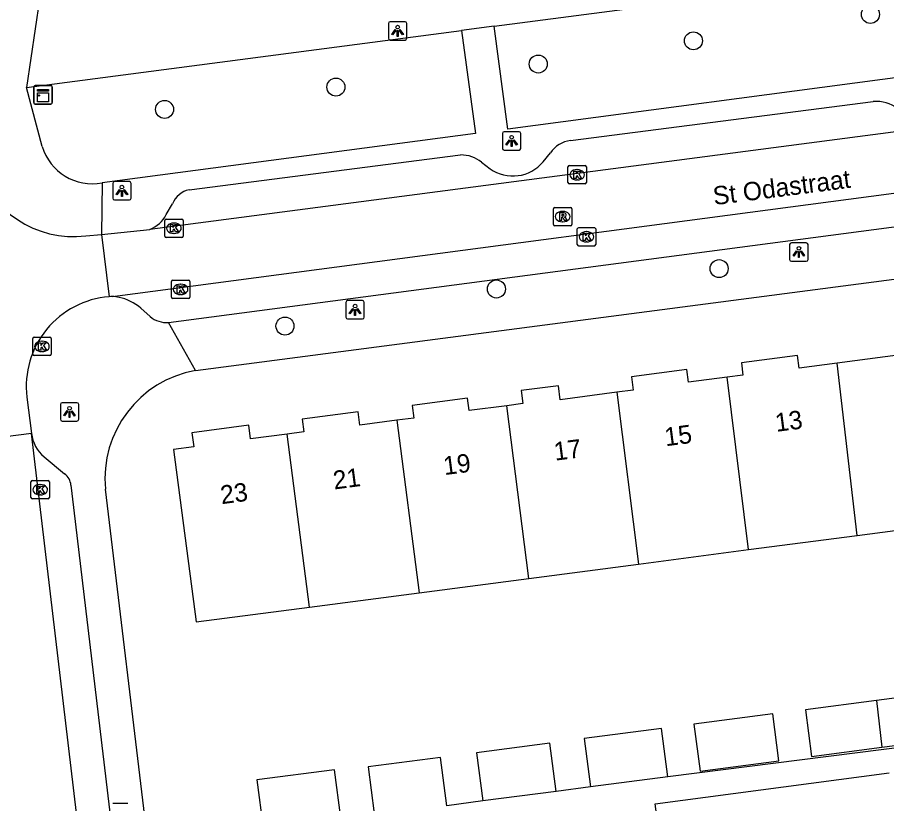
# Model space of a CAD drawing. Extents: x 162074 to 163034, y 381824 to 382557.
# Drawn here: x 162347.28 to 162394.48, y 382422.66 to 382465.37 of the extents above; entities that cross this region are included whole.
import ezdxf

# ---------------------------------------------------------------- set-up
doc = ezdxf.new("R2010")
doc.units = 0
for name, color, linetype in [('IMGEO_Boom', 7, 'Continuous'), ('IMGEO_Kast', 7, 'Continuous'), ('IMGEO_Kolk', 7, 'Continuous'), ('IMGEO_Lichtpunt', 7, 'Continuous'), ('IMGEO_Openbare_ruimte_label', 7, 'Continuous'), ('IMGEO_Pand', 7, 'Continuous'), ('IMGEO_Pand_nummerreeks', 7, 'Continuous'), ('IMGEO_Rijbaan_lokaal_open', 7, 'Continuous'), ('IMGEO_Rioolput', 7, 'Continuous'), ('IMGEO_Voetpad_open', 7, 'Continuous')]:
    doc.layers.add(name, color=color, linetype=linetype)

msp = doc.modelspace()

# ---------------------------------------------------------------- linework, layer by layer
at = {"layer": 'IMGEO_Boom'}
for centre in [(162393.602, 382465.53), (162383.992, 382464.098), (162375.562, 382462.838), (162364.577, 382461.583), (162355.268, 382460.371), (162385.387, 382451.722), (162373.292, 382450.616), (162361.81, 382448.6)]:
    msp.add_circle(centre, 0.489, dxfattribs=at)
at = {"layer": 'IMGEO_Kast'}
for p, q in [((162348.168, 382460.739), (162348.168, 382461.58)), ((162348.168, 382461.58), (162348.168, 382460.739)), ((162348.243, 382461.664), (162349.084, 382461.664)), ((162349.084, 382461.664), (162348.243, 382461.664)), ((162349.168, 382461.589), (162349.168, 382460.748)), ((162349.168, 382460.748), (162349.168, 382461.589)), ((162349.093, 382460.664), (162348.252, 382460.664)), ((162348.252, 382460.664), (162349.093, 382460.664))]:
    msp.add_line(p, q, dxfattribs=at)
for points in [[(162348.363, 382461.454), (162348.963, 382461.454), (162348.963, 382461.369), (162348.363, 382461.369), (162348.363, 382461.454)], [(162348.363, 382461.279), (162348.963, 382461.279), (162348.963, 382460.79), (162348.363, 382460.79), (162348.363, 382461.279)]]:
    msp.add_lwpolyline(points, dxfattribs=at)
msp.add_circle((162348.447, 382461.128), 0.0377, dxfattribs=at)
for centre, start, end in [((162348.246, 382461.586), 92.4484, 184.2845), ((162348.246, 382461.586), 92.4484, 184.2845), ((162349.09, 382461.586), 2.4484, 94.2845), ((162349.09, 382461.586), 2.4484, 94.2845), ((162348.246, 382460.742), 182.4484, 274.2845), ((162348.246, 382460.742), 182.4484, 274.2845), ((162349.09, 382460.742), 272.4484, 4.2845), ((162349.09, 382460.742), 272.4484, 4.2845)]:
    msp.add_arc(centre, 0.0779, start, end, dxfattribs=at)
at = {"layer": 'IMGEO_Kolk'}
for p, q in [((162377.175, 382456.395), (162377.175, 382457.247)), ((162377.25, 382457.321), (162378.102, 382457.321)), ((162378.176, 382457.247), (162378.176, 382456.395)), ((162377.663, 382457.101), (162377.688, 382457.101)), ((162378.102, 382456.321), (162377.25, 382456.321)), ((162377.686, 382456.541), (162377.661, 382456.541)), ((162355.277, 382453.488), (162355.277, 382454.34)), ((162355.352, 382454.414), (162356.204, 382454.414)), ((162356.278, 382454.34), (162356.278, 382453.488)), ((162355.765, 382454.194), (162355.79, 382454.194)), ((162377.683, 382453.025), (162377.683, 382453.877)), ((162377.758, 382453.951), (162378.61, 382453.951)), ((162378.684, 382453.877), (162378.684, 382453.025)), ((162356.204, 382453.414), (162355.352, 382453.414)), ((162355.788, 382453.634), (162355.763, 382453.634)), ((162378.171, 382453.731), (162378.196, 382453.731)), ((162378.61, 382452.951), (162377.758, 382452.951)), ((162378.194, 382453.171), (162378.169, 382453.171)), ((162355.639, 382450.169), (162355.639, 382451.021)), ((162355.714, 382451.095), (162356.566, 382451.095)), ((162356.64, 382451.021), (162356.64, 382450.169)), ((162356.127, 382450.875), (162356.152, 382450.875)), ((162356.566, 382450.095), (162355.714, 382450.095)), ((162356.15, 382450.315), (162356.125, 382450.315)), ((162348.11, 382447.071), (162348.11, 382447.923)), ((162348.185, 382447.997), (162349.037, 382447.997)), ((162348.598, 382447.777), (162348.623, 382447.777)), ((162349.111, 382447.923), (162349.111, 382447.071)), ((162348.621, 382447.217), (162348.596, 382447.217)), ((162349.037, 382446.997), (162348.185, 382446.997)), ((162348.015, 382439.284), (162348.015, 382440.136)), ((162348.09, 382440.21), (162348.942, 382440.21)), ((162349.016, 382440.136), (162349.016, 382439.284)), ((162348.503, 382439.99), (162348.528, 382439.99)), ((162348.942, 382439.21), (162348.09, 382439.21)), ((162348.526, 382439.43), (162348.501, 382439.43))]:
    msp.add_line(p, q, dxfattribs=at)
for points in [[(162377.175, 382456.395), (162377.175, 382457.247)], [(162377.25, 382457.321), (162378.102, 382457.321)], [(162378.176, 382457.247), (162378.176, 382456.395)], [(162377.496, 382457.021), (162377.619, 382457.021), (162377.619, 382456.87), (162377.749, 382457.021), (162377.913, 382457.021), (162377.767, 382456.87), (162377.92, 382456.621), (162377.768, 382456.621), (162377.683, 382456.785), (162377.619, 382456.718), (162377.619, 382456.621), (162377.496, 382456.621), (162377.496, 382457.021)], [(162378.102, 382456.321), (162377.25, 382456.321)], [(162355.277, 382453.488), (162355.277, 382454.34)], [(162355.352, 382454.414), (162356.204, 382454.414)], [(162356.278, 382454.34), (162356.278, 382453.488)], [(162355.598, 382454.114), (162355.721, 382454.114), (162355.721, 382453.963), (162355.851, 382454.114), (162356.015, 382454.114), (162355.869, 382453.963), (162356.022, 382453.714), (162355.87, 382453.714), (162355.785, 382453.878), (162355.721, 382453.811), (162355.721, 382453.714), (162355.598, 382453.714), (162355.598, 382454.114)], [(162377.683, 382453.025), (162377.683, 382453.877)], [(162377.758, 382453.951), (162378.61, 382453.951)], [(162378.684, 382453.877), (162378.684, 382453.025)], [(162356.204, 382453.414), (162355.352, 382453.414)], [(162378.004, 382453.651), (162378.127, 382453.651), (162378.127, 382453.5), (162378.257, 382453.651), (162378.421, 382453.651), (162378.275, 382453.5), (162378.428, 382453.251), (162378.276, 382453.251), (162378.191, 382453.415), (162378.127, 382453.348), (162378.127, 382453.251), (162378.004, 382453.251), (162378.004, 382453.651)], [(162378.61, 382452.951), (162377.758, 382452.951)], [(162355.639, 382450.169), (162355.639, 382451.021)], [(162355.714, 382451.095), (162356.566, 382451.095)], [(162356.64, 382451.021), (162356.64, 382450.169)], [(162355.96, 382450.795), (162356.083, 382450.795), (162356.083, 382450.644), (162356.213, 382450.795), (162356.377, 382450.795), (162356.231, 382450.644), (162356.384, 382450.395), (162356.232, 382450.395), (162356.147, 382450.559), (162356.083, 382450.492), (162356.083, 382450.395), (162355.96, 382450.395), (162355.96, 382450.795)], [(162356.566, 382450.095), (162355.714, 382450.095)], [(162348.11, 382447.071), (162348.11, 382447.923)], [(162348.185, 382447.997), (162349.037, 382447.997)], [(162348.431, 382447.697), (162348.554, 382447.697), (162348.554, 382447.546), (162348.684, 382447.697), (162348.848, 382447.697), (162348.702, 382447.546), (162348.855, 382447.297), (162348.703, 382447.297), (162348.618, 382447.461), (162348.554, 382447.394), (162348.554, 382447.297), (162348.431, 382447.297), (162348.431, 382447.697)], [(162349.111, 382447.923), (162349.111, 382447.071)], [(162349.037, 382446.997), (162348.185, 382446.997)], [(162348.015, 382439.284), (162348.015, 382440.136)], [(162348.09, 382440.21), (162348.942, 382440.21)], [(162349.016, 382440.136), (162349.016, 382439.284)], [(162348.336, 382439.91), (162348.459, 382439.91), (162348.459, 382439.759), (162348.589, 382439.91), (162348.753, 382439.91), (162348.607, 382439.759), (162348.76, 382439.51), (162348.608, 382439.51), (162348.523, 382439.674), (162348.459, 382439.607), (162348.459, 382439.51), (162348.336, 382439.51), (162348.336, 382439.91)], [(162348.942, 382439.21), (162348.09, 382439.21)]]:
    msp.add_lwpolyline(points, dxfattribs=at)
for centre, start, end in [((162377.252, 382457.245), 91.552, 178.448), ((162377.252, 382457.245), 91.552, 178.448), ((162378.1, 382457.245), 1.552, 88.448), ((162378.1, 382457.245), 1.552, 88.448), ((162377.252, 382456.397), 181.552, 268.448), ((162377.252, 382456.397), 181.552, 268.448), ((162378.1, 382456.397), 271.552, 358.448), ((162378.1, 382456.397), 271.552, 358.448), ((162355.354, 382454.338), 91.552, 178.448), ((162355.354, 382454.338), 91.552, 178.448), ((162356.202, 382454.338), 1.552, 88.448), ((162356.202, 382454.338), 1.552, 88.448), ((162377.76, 382453.875), 91.552, 178.448), ((162377.76, 382453.875), 91.552, 178.448), ((162378.608, 382453.875), 1.552, 88.448), ((162378.608, 382453.875), 1.552, 88.448), ((162355.354, 382453.49), 181.552, 268.448), ((162355.354, 382453.49), 181.552, 268.448), ((162356.202, 382453.49), 271.552, 358.448), ((162356.202, 382453.49), 271.552, 358.448), ((162377.76, 382453.027), 181.552, 268.448), ((162377.76, 382453.027), 181.552, 268.448), ((162378.608, 382453.027), 271.552, 358.448), ((162378.608, 382453.027), 271.552, 358.448), ((162355.716, 382451.019), 91.552, 178.448), ((162355.716, 382451.019), 91.552, 178.448), ((162356.564, 382451.019), 1.552, 88.448), ((162356.564, 382451.019), 1.552, 88.448), ((162355.716, 382450.171), 181.552, 268.448), ((162355.716, 382450.171), 181.552, 268.448), ((162356.564, 382450.171), 271.552, 358.448), ((162356.564, 382450.171), 271.552, 358.448), ((162348.187, 382447.921), 91.552, 178.448), ((162348.187, 382447.921), 91.552, 178.448), ((162349.035, 382447.921), 1.552, 88.448), ((162349.035, 382447.921), 1.552, 88.448), ((162348.187, 382447.073), 181.552, 268.448), ((162348.187, 382447.073), 181.552, 268.448), ((162349.035, 382447.073), 271.552, 358.448), ((162349.035, 382447.073), 271.552, 358.448), ((162348.092, 382440.134), 91.552, 178.448), ((162348.092, 382440.134), 91.552, 178.448), ((162348.94, 382440.134), 1.552, 88.448), ((162348.94, 382440.134), 1.552, 88.448), ((162348.092, 382439.286), 181.552, 268.448), ((162348.092, 382439.286), 181.552, 268.448), ((162348.94, 382439.286), 271.552, 358.448), ((162348.94, 382439.286), 271.552, 358.448)]:
    msp.add_arc(centre, 0.0765, start, end, dxfattribs=at)
for centre, major_axis, ratio, start_param, end_param in [((162377.662, 382456.821), (-0.387, 0.002), 0.722429, 4.712389, 7.853982), ((162377.687, 382456.821), (-0.39, 0.002), 0.717154, 1.570796, 4.712389), ((162355.764, 382453.914), (-0.387, 0.002), 0.722429, 4.712389, 7.853982), ((162355.789, 382453.914), (-0.39, 0.002), 0.717154, 1.570796, 4.712389), ((162378.17, 382453.451), (-0.387, 0.002), 0.722429, 4.712389, 7.853982), ((162378.195, 382453.451), (-0.39, 0.002), 0.717154, 1.570796, 4.712389), ((162356.126, 382450.595), (-0.387, 0.002), 0.722429, 4.712389, 7.853982), ((162356.151, 382450.595), (-0.39, 0.002), 0.717154, 1.570796, 4.712389), ((162348.597, 382447.497), (-0.387, 0.002), 0.722429, 4.712389, 7.853982), ((162348.622, 382447.497), (-0.39, 0.002), 0.717154, 1.570796, 4.712389), ((162348.502, 382439.71), (-0.387, 0.002), 0.722429, 4.712389, 7.853982), ((162348.527, 382439.71), (-0.39, 0.002), 0.717154, 1.570796, 4.712389)]:
    msp.add_ellipse(centre, major_axis=major_axis, ratio=ratio, start_param=start_param, end_param=end_param, dxfattribs=at)
at = {"layer": 'IMGEO_Lichtpunt'}
for p, q in [((162368.33, 382465.137), (162367.522, 382465.137)), ((162368.33, 382465.137), (162367.522, 382465.137)), ((162367.428, 382465.042), (162367.428, 382464.235)), ((162367.428, 382465.042), (162367.428, 382464.235)), ((162368.424, 382464.235), (162368.424, 382465.042)), ((162368.424, 382464.235), (162368.424, 382465.042)), ((162367.522, 382464.141), (162368.33, 382464.141)), ((162367.522, 382464.141), (162368.33, 382464.141)), ((162373.619, 382459.06), (162373.619, 382458.253)), ((162373.619, 382459.06), (162373.619, 382458.253)), ((162374.521, 382459.155), (162373.713, 382459.155)), ((162374.521, 382459.155), (162373.713, 382459.155)), ((162374.615, 382458.253), (162374.615, 382459.06)), ((162374.615, 382458.253), (162374.615, 382459.06)), ((162373.713, 382458.159), (162374.521, 382458.159)), ((162373.713, 382458.159), (162374.521, 382458.159)), ((162352.457, 382456.353), (162352.457, 382455.546)), ((162352.457, 382456.353), (162352.457, 382455.546)), ((162353.359, 382456.448), (162352.551, 382456.448)), ((162353.359, 382456.448), (162352.551, 382456.448)), ((162353.453, 382455.546), (162353.453, 382456.353)), ((162353.453, 382455.546), (162353.453, 382456.353)), ((162352.551, 382455.452), (162353.359, 382455.452)), ((162352.551, 382455.452), (162353.359, 382455.452)), ((162389.216, 382453.029), (162389.216, 382452.222)), ((162389.216, 382453.029), (162389.216, 382452.222)), ((162390.118, 382453.124), (162389.31, 382453.124)), ((162390.118, 382453.124), (162389.31, 382453.124)), ((162390.212, 382452.222), (162390.212, 382453.029)), ((162390.212, 382452.222), (162390.212, 382453.029)), ((162389.31, 382452.128), (162390.118, 382452.128)), ((162389.31, 382452.128), (162390.118, 382452.128)), ((162365.115, 382449.89), (162365.115, 382449.083)), ((162365.115, 382449.89), (162365.115, 382449.083)), ((162366.017, 382449.985), (162365.209, 382449.985)), ((162366.017, 382449.985), (162365.209, 382449.985)), ((162366.111, 382449.083), (162366.111, 382449.89)), ((162366.111, 382449.083), (162366.111, 382449.89)), ((162365.209, 382448.989), (162366.017, 382448.989)), ((162365.209, 382448.989), (162366.017, 382448.989)), ((162350.513, 382444.438), (162349.705, 382444.438)), ((162350.513, 382444.438), (162349.705, 382444.438)), ((162349.611, 382444.343), (162349.611, 382443.536)), ((162349.611, 382444.343), (162349.611, 382443.536)), ((162350.607, 382443.536), (162350.607, 382444.343)), ((162350.607, 382443.536), (162350.607, 382444.343)), ((162349.705, 382443.442), (162350.513, 382443.442)), ((162349.705, 382443.442), (162350.513, 382443.442)), ((162353.269, 382422.66), (162352.461, 382422.66)), ((162353.269, 382422.66), (162352.461, 382422.66))]:
    msp.add_line(p, q, dxfattribs=at)
for points in [[(162367.802, 382464.706), (162367.841, 382464.678), (162367.653, 382464.416), (162367.615, 382464.443), (162367.802, 382464.706)], [(162368.014, 382464.678), (162368.052, 382464.705), (162368.239, 382464.443), (162368.2, 382464.415), (162368.014, 382464.678)], [(162367.904, 382464.658), (162367.951, 382464.658), (162367.951, 382464.336), (162367.904, 382464.336), (162367.904, 382464.658)], [(162373.993, 382458.724), (162374.032, 382458.696), (162373.844, 382458.434), (162373.806, 382458.461), (162373.993, 382458.724)], [(162374.095, 382458.676), (162374.142, 382458.676), (162374.142, 382458.354), (162374.095, 382458.354), (162374.095, 382458.676)], [(162374.205, 382458.696), (162374.243, 382458.723), (162374.43, 382458.461), (162374.391, 382458.433), (162374.205, 382458.696)], [(162352.831, 382456.017), (162352.87, 382455.989), (162352.682, 382455.727), (162352.644, 382455.754), (162352.831, 382456.017)], [(162352.933, 382455.969), (162352.98, 382455.969), (162352.98, 382455.647), (162352.933, 382455.647), (162352.933, 382455.969)], [(162353.043, 382455.989), (162353.081, 382456.016), (162353.268, 382455.754), (162353.229, 382455.726), (162353.043, 382455.989)], [(162389.59, 382452.693), (162389.629, 382452.665), (162389.441, 382452.403), (162389.403, 382452.43), (162389.59, 382452.693)], [(162389.692, 382452.645), (162389.739, 382452.645), (162389.739, 382452.323), (162389.692, 382452.323), (162389.692, 382452.645)], [(162389.802, 382452.665), (162389.84, 382452.692), (162390.027, 382452.43), (162389.988, 382452.402), (162389.802, 382452.665)], [(162365.489, 382449.554), (162365.528, 382449.526), (162365.34, 382449.264), (162365.302, 382449.291), (162365.489, 382449.554)], [(162365.591, 382449.506), (162365.638, 382449.506), (162365.638, 382449.184), (162365.591, 382449.184), (162365.591, 382449.506)], [(162365.701, 382449.526), (162365.739, 382449.553), (162365.926, 382449.291), (162365.887, 382449.263), (162365.701, 382449.526)], [(162349.985, 382444.007), (162350.024, 382443.979), (162349.836, 382443.717), (162349.798, 382443.744), (162349.985, 382444.007)], [(162350.087, 382443.959), (162350.134, 382443.959), (162350.134, 382443.637), (162350.087, 382443.637), (162350.087, 382443.959)], [(162350.197, 382443.979), (162350.235, 382444.006), (162350.422, 382443.744), (162350.383, 382443.716), (162350.197, 382443.979)]]:
    msp.add_lwpolyline(points, dxfattribs=at)
for centre in [(162367.927, 382464.84), (162374.118, 382458.858), (162352.956, 382456.151), (162389.715, 382452.827), (162365.614, 382449.688), (162350.11, 382444.141)]:
    msp.add_circle(centre, 0.0994, dxfattribs=at)
for centre, start, end in [((162367.522, 382465.042), 90, 180), ((162367.522, 382465.042), 90, 180), ((162368.33, 382465.042), 0, 90), ((162368.33, 382465.042), 0, 90), ((162367.522, 382464.235), 180, 270), ((162367.522, 382464.235), 180, 270), ((162368.33, 382464.235), 270, 0), ((162368.33, 382464.235), 270, 360), ((162373.713, 382459.06), 90, 180), ((162373.713, 382459.06), 90, 180), ((162374.521, 382459.06), 0, 90), ((162374.521, 382459.06), 0, 90), ((162373.713, 382458.253), 180, 270), ((162373.713, 382458.253), 180, 270), ((162374.521, 382458.253), 270, 0), ((162374.521, 382458.253), 270, 360), ((162352.551, 382456.353), 90, 180), ((162352.551, 382456.353), 90, 180), ((162353.359, 382456.353), 0, 90), ((162353.359, 382456.353), 0, 90), ((162352.551, 382455.546), 180, 270), ((162352.551, 382455.546), 180, 270), ((162353.359, 382455.546), 270, 0), ((162353.359, 382455.546), 270, 360), ((162389.31, 382453.029), 90, 180), ((162389.31, 382453.029), 90, 180), ((162390.118, 382453.029), 0, 90), ((162390.118, 382453.029), 0, 90), ((162389.31, 382452.222), 180, 270), ((162389.31, 382452.222), 180, 270), ((162390.118, 382452.222), 270, 0), ((162390.118, 382452.222), 270, 360), ((162365.209, 382449.89), 90, 180), ((162365.209, 382449.89), 90, 180), ((162366.017, 382449.89), 0, 90), ((162366.017, 382449.89), 0, 90), ((162365.209, 382449.083), 180, 270), ((162365.209, 382449.083), 180, 270), ((162366.017, 382449.083), 270, 0), ((162366.017, 382449.083), 270, 360), ((162349.705, 382444.343), 90, 180), ((162349.705, 382444.343), 90, 180), ((162350.513, 382444.343), 0, 90), ((162350.513, 382444.343), 0, 90), ((162349.705, 382443.536), 180, 270), ((162349.705, 382443.536), 180, 270), ((162350.513, 382443.536), 270, 0), ((162350.513, 382443.536), 270, 360)]:
    msp.add_arc(centre, 0.0946, start, end, dxfattribs=at)
at = {"layer": 'IMGEO_Pand'}
for points in [[(162392.89, 382437.23), (162404.853, 382438.794), (162404.44, 382441.957), (162398.784, 382441.218), (162397.976, 382447.401), (162391.801, 382446.593)], [(162391.801, 382446.593), (162389.725, 382446.322), (162389.637, 382446.996), (162386.592, 382446.598), (162386.679, 382445.934), (162385.824, 382445.822)], [(162392.89, 382437.23), (162391.801, 382446.593)], [(162385.824, 382445.822), (162383.726, 382445.548), (162383.635, 382446.244), (162380.628, 382445.851), (162380.723, 382445.123), (162379.833, 382445.006)], [(162386.972, 382436.456), (162385.824, 382445.822)], [(162379.833, 382445.006), (162376.76, 382444.604), (162376.661, 382445.364), (162374.642, 382445.1), (162374.734, 382444.392), (162373.862, 382444.278)], [(162379.833, 382445.006), (162381.014, 382435.677)], [(162373.862, 382444.278), (162371.814, 382444.01), (162371.726, 382444.682), (162368.714, 382444.288), (162368.803, 382443.603), (162367.889, 382443.484)], [(162367.889, 382443.484), (162365.878, 382443.221), (162365.783, 382443.943), (162362.749, 382443.547), (162362.839, 382442.857), (162361.935, 382442.739)], [(162375.057, 382434.898), (162373.862, 382444.278)], [(162367.889, 382443.484), (162369.099, 382434.119)], [(162361.935, 382442.739), (162359.943, 382442.478), (162359.846, 382443.215), (162356.757, 382442.811), (162356.859, 382442.037), (162355.76, 382441.893), (162356.984, 382432.535), (162363.15, 382433.341)], [(162363.15, 382433.341), (162361.935, 382442.739)], [(162386.972, 382436.456), (162392.89, 382437.23)], [(162381.014, 382435.677), (162386.972, 382436.456)], [(162375.057, 382434.898), (162381.014, 382435.677)], [(162369.099, 382434.119), (162375.057, 382434.898)], [(162363.15, 382433.341), (162369.099, 382434.119)], [(162394.228, 382425.722), (162398.434, 382426.272), (162398.101, 382428.812), (162393.933, 382428.266)], [(162393.933, 382428.266), (162390.075, 382427.762), (162390.408, 382425.223), (162394.228, 382425.722)], [(162393.933, 382428.266), (162394.228, 382425.722)], [(162388.627, 382424.99), (162388.295, 382427.529), (162384.019, 382426.97), (162384.351, 382424.43), (162388.627, 382424.99)], [(162382.601, 382424.117), (162382.258, 382426.74), (162378.063, 382426.191), (162378.405, 382423.569)], [(162376.532, 382423.323), (162376.197, 382425.947), (162372.209, 382425.425), (162372.552, 382422.803)], [(162370.594, 382422.547), (162370.255, 382425.17), (162366.319, 382424.655), (162366.651, 382422.117)], [(162364.846, 382421.889), (162364.504, 382424.503), (162360.286, 382423.951), (162360.628, 382421.338)], [(162382.601, 382424.117), (162378.405, 382423.569)], [(162376.532, 382423.323), (162372.552, 382422.803)]]:
    msp.add_lwpolyline(points, dxfattribs=at)
at = {"layer": 'IMGEO_Rijbaan_lokaal_open'}
for points in [[(162463.823, 382468.189), (162354.468, 382453.854)], [(162352.448, 382450.209), (162401.436, 382456.696)], [(162351.85, 382453.585), (162354.468, 382453.854)], [(162350.989, 382453.496), (162351.85, 382453.585)], [(162351.85, 382453.585), (162352.256, 382450.197)], [(162352.448, 382450.209), (162352.352, 382450.204), (162352.256, 382450.197)], [(162347.791, 382444.746), (162348.044, 382442.765)], [(162348.044, 382442.765), (162343.079, 382442.137)], [(162359.505, 382347.328), (162351.073, 382417.25), (162348.044, 382442.765)]]:
    msp.add_lwpolyline(points, dxfattribs=at)
for centre, radius, start, end in [((162350.348, 382459.007), 5.548, 196.1891, 276.6348), ((162352.649, 382445.321), 4.892, 94.6048, 186.7523)]:
    msp.add_arc(centre, radius, start, end, dxfattribs=at)
at = {"layer": 'IMGEO_Rioolput'}
for p, q in [((162376.389, 382454.124), (162376.389, 382454.976)), ((162376.464, 382455.05), (162377.316, 382455.05)), ((162376.877, 382454.83), (162376.902, 382454.83)), ((162377.39, 382454.976), (162377.39, 382454.124)), ((162377.316, 382454.05), (162376.464, 382454.05)), ((162376.9, 382454.27), (162376.875, 382454.27))]:
    msp.add_line(p, q, dxfattribs=at)
for points in [[(162376.389, 382454.124), (162376.389, 382454.976)], [(162376.464, 382455.05), (162377.316, 382455.05)], [(162376.978, 382454.748), (162376.726, 382454.75), (162376.726, 382454.35)], [(162377.39, 382454.976), (162377.39, 382454.124)], [(162376.726, 382454.35), (162376.85, 382454.35), (162376.85, 382454.512), (162376.861, 382454.512)], [(162376.904, 382454.669), (162376.85, 382454.669), (162376.85, 382454.588)], [(162376.85, 382454.588), (162376.902, 382454.588)], [(162376.908, 382454.483), (162376.979, 382454.35), (162377.119, 382454.35), (162377.054, 382454.476)], [(162377.316, 382454.05), (162376.464, 382454.05)]]:
    msp.add_lwpolyline(points, dxfattribs=at)
for centre, radius, start, end in [((162376.466, 382454.974), 0.0765, 91.552, 178.448), ((162376.466, 382454.974), 0.0765, 91.552, 178.448), ((162377.314, 382454.974), 0.0765, 1.552, 88.448), ((162377.314, 382454.974), 0.0765, 1.552, 88.448), ((162376.86, 382454.459), 0.0533, 26.0293, 88.6989), ((162376.886, 382454.777), 0.19, 274.7715, 282.9687), ((162376.91, 382454.573), 0.0964, 77.0061, 93.1865), ((162376.924, 382454.63), 0.0378, 276.6634, 79.6772), ((162376.977, 382454.638), 0.109, 350.3612, 89.416), ((162376.975, 382454.638), 0.112, 277.5842, 350.9817), ((162376.959, 382454.423), 0.108, 29.5134, 73.7905), ((162376.466, 382454.126), 0.0765, 181.552, 268.448), ((162376.466, 382454.126), 0.0765, 181.552, 268.448), ((162377.314, 382454.126), 0.0765, 271.552, 358.448), ((162377.314, 382454.126), 0.0765, 271.552, 358.448)]:
    msp.add_arc(centre, radius, start, end, dxfattribs=at)
for centre, major_axis, ratio, start_param, end_param in [((162376.876, 382454.55), (-0.387, 0.002), 0.722429, 4.712389, 7.853982), ((162376.901, 382454.55), (-0.39, 0.002), 0.717154, 1.570796, 4.712389)]:
    msp.add_ellipse(centre, major_axis=major_axis, ratio=ratio, start_param=start_param, end_param=end_param, dxfattribs=at)
at = {"layer": 'IMGEO_Voetpad_open'}
for points in [[(162395.012, 382467.752), (162395.761, 382462.198), (162373.908, 382459.306), (162373.173, 382464.892)], [(162373.173, 382464.892), (162395.012, 382467.752)], [(162348.481, 382466.366), (162347.775, 382461.567)], [(162373.173, 382464.892), (162371.398, 382464.66)], [(162347.775, 382461.567), (162371.398, 382464.66)], [(162371.398, 382464.66), (162372.148, 382459.072), (162351.881, 382456.381)], [(162348.625, 382458.359), (162347.775, 382461.567)], [(162377.322, 382458.678), (162393.757, 382460.799)], [(162356.601, 382456.004), (162371.35, 382457.896)], [(162375.832, 382457.532), (162376.222, 382458.012)], [(162372.483, 382457.503), (162372.944, 382457.146)], [(162351.881, 382456.381), (162351.85, 382453.585)], [(162355.361, 382454.66), (162355.708, 382455.246)], [(162355.483, 382448.801), (162398.733, 382454.496)], [(162356.958, 382446.183), (162398.07, 382451.559)], [(162354.493, 382449.117), (162353.976, 382449.566)], [(162356.958, 382446.183), (162355.483, 382448.801)], [(162348.727, 382441.502), (162349.842, 382440.581)], [(162350.184, 382439.951), (162352.789, 382418.064), (162354.1, 382407.187), (162353.149, 382407.065)], [(162354.358, 382420.586), (162352.061, 382439.747)], [(162407.339, 382427.254), (162382.601, 382424.117)], [(162382.202, 382420.455), (162381.911, 382422.653), (162394.612, 382424.336)], [(162378.405, 382423.569), (162376.532, 382423.323)], [(162372.552, 382422.803), (162370.594, 382422.547)]]:
    msp.add_lwpolyline(points, dxfattribs=at)
for centre, radius, start, end in [((162393.922, 382458.922), 1.884, 51.7614, 95.0219), ((162377.494, 382457.153), 1.535, 96.4286, 145.9574), ((162351.357, 382459.187), 2.855, 196.863, 280.5801), ((162371.395, 382456.197), 1.7, 50.212, 91.5281), ((162374.18, 382458.897), 2.143, 234.7845, 320.4412), ((162356.854, 382454.801), 1.229, 101.8757, 158.7751), ((162353.853, 382455.433), 1.694, 291.2719, 332.8654), ((162352.286, 382447.635), 2.579, 78.5775, 86.4053), ((162352.295, 382447.708), 2.506, 47.8555, 78.4327), ((162355.369, 382450.154), 1.358, 229.7986, 274.7961), ((162357.987, 382440.319), 5.954, 99.9538, 185.5129), ((162349.995, 382443.004), 1.966, 186.9815, 229.8254), ((162349.331, 382439.896), 0.855, 3.7124, 53.2789)]:
    msp.add_arc(centre, radius, start, end, dxfattribs=at)

# ---------------------------------------------------------------- texts
at = {"layer": 'IMGEO_Openbare_ruimte_label'}
msp.add_text('St Odastraat', height=1, rotation=7.2956, dxfattribs=at).set_placement((162385.117, 382455.168))
at = {"layer": 'IMGEO_Pand_nummerreeks'}
for s, p in [('13', (162388.492, 382442.854)), ('15', (162382.486, 382442.071)), ('17', (162376.479, 382441.287)), ('19', (162370.472, 382440.504)), ('21', (162364.487, 382439.723)), ('23', (162358.368, 382438.925))]:
    msp.add_text(s, height=1, rotation=7.4306, dxfattribs=at).set_placement(p)

doc.saveas('drawing.dxf')
